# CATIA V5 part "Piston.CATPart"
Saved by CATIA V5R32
Part number: Piston
Bounding box of the stored display mesh (mm): x -46 to 46, y -45.932 to 45.932, z 0 to 70.683
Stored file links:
  D:\PROJECTS\Project 2022\CATIA V5 6R 2022\Resources\Part Files\c13_catia_v5_6r2022_prt\c13_catia_v5-6r2022_figr_13-41\Part & Asm files\Piston.CATPart
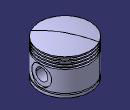
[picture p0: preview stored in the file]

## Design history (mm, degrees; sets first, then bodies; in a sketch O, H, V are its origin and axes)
Body1 (main body)
  Sketch1 on yz-plane, origin (0, 0, 0), H (0, 1, 0), V (0, 0, 1)
    line L1 (37, 0) -> (46, 0)
    line L2 (46, 0) -> (46, 5)
    construction line L3 (0, 62) -> (0, 0)
    point P2 (46, 65)
    line L4 (42.5, 45) -> (42.5, 48)
    point P5 (46, 48)
    point P6 (46, 50)
    point P7 (46, 53)
    point P8 (46, 55)
    point P9 (46, 58)
    point P10 (46, 60)
    line L5 (42.5, 48) -> (46, 48)
    line L6 (42.5, 45) -> (46, 45)
    line L7 (42.5, 50) -> (46, 50)
    point P13 (42.5, 50)
    line L8 (42.5, 53) -> (46, 53)
    point P14 (42.5, 53)
    line L9 (42.5, 55) -> (46, 55)
    point P15 (42.5, 55)
    line L10 (42.5, 58) -> (46, 58)
    point P16 (42.5, 58)
    line L11 (42.5, 60) -> (46, 60)
    point P17 (42.5, 60)
    line L12 (46, 48) -> (46, 50)
    line L13 (46, 53) -> (46, 55)
    line L14 (46, 58) -> (46, 60)
    line L15 (42.5, 50) -> (42.5, 53)
    line L16 (42.5, 55) -> (42.5, 58)
    line L17 (42.5, 60) -> (42.5, 63)
    line L18 (42.5, 63) -> (46, 63)
    point P18 (46, 63)
    line L19 (46, 63) -> (46, 65)
    line L20 (46, 5) -> (42.5, 5)
    point P20 (42.5, 5)
    line L21 (42.5, 5) -> (42.5, 7)
    line L22 (42.5, 7) -> (46, 7)
    point P22 (46, 7)
    line L23 (46, 7) -> (46, 45)
    point P23 (-46, 65)
    point P24 (-46, 63)
    construction line L24 (-46, 63) -> (-46, 65)
    arc A1 centre (0, -118.3167) radius 189 from (46, 65) to (0, 70.6833) ccw
    point P26 (0, 55)
    line L25 (37, 0) -> (37, 62)
    line L26 (37, 62) -> (0, 62)
    line L27 (0, 62) -> (0, 70.6833)
    construction arc A2 centre (0, -118.3167) radius 189 from (0, 70.6833) to (-46, 65) ccw
    distance L2 L4 = 3.5
    distance L6 L1 = 45
    length L4 = 3
    length L15 = 3
    length L16 = 3
    length L13 = 2
    length L12 = 2
    length L17 = 3
    length L19 = 2
    length L14 = 2
    length L21 = 2
    distance L1 L22 = 7
    radius A1 = 189
    length L26 = 37
    length L25 = 62
    distance L2 L3 = 46
    horizontal: L1 H, L5 H, L6 H, L7 H, L8 H, L9 H, L10 H, L11 H, L18 H, L20 H, L22 H, L26 H
    vertical: L2 V, L3 V, L12 V, L13 V, L14 V, L19 V, L21 V, L23 V, L25 V, L27 V, L17 V, L16 V, L15 V, L4 V
    coincidence: L2 P5, L2 P6, L2 P7, L2 P8, L2 P9, L2 P10, L4 P13, L4 P14, L4 P15, L4 P16, L4 P17, L2 L12, L12 L13, L13 L14, L4 L15, L15 L16, L16 L17, P18 L14, L14 L19, P20 L15, P22 L2, L2 L23, P26 L3, P26 L9, L1 H, A1 A2
    symmetry: P2 P23 L3, P18 P24 L3, L19 L24 L3
  Shaft1: profile Sketch1, axis Sketch1.V, angle 360
  Sketch2 on yz-plane, origin (0, 0, 0), H (0, 1, 0), V (0, 0, 1)
    circle A1 centre (0, 26) radius 19.5
    point P1 (0, 26)
    radius A1 = 19.5
    distance H P1 = 26
    coincidence: P1 V
  Pad1: profile Sketch2, direction (1, 0, 0), up to the existing solid (limit type 2), opposite side length -25
  Mirror1: of Pad1, Sketch2, about yz-plane
  Sketch3 on yz-plane, origin (0, 0, 0), H (0, 1, 0), V (0, 0, 1)
    circle A1 centre (0, 26) radius 18
    point P1 (0, 26)
    reference projected circle E1 centre (0, 26) radius 19.5 from edge of Pad1
    radius A1 = 18
    coincidence: P1 V
    concentricity: A1 E1
  Pocket1: profile Sketch3, direction (-1, 0, 0), length 42.5, opposite side length -50
  Mirror2: of Pocket1, Sketch3, about yz-plane
  Sketch4 on yz-plane, origin (0, 0, 0), H (0, 1, 0), V (0, 0, 1)
    circle A1 centre (0, 26) radius 11
    point P1 (0, 26)
    reference projected circle E1 centre (0, 26) radius 19.5 from edge of Pad1
    radius A1 = 11
    coincidence: P1 V
    concentricity: A1 E1
  Pocket2: profile Sketch4, direction (-1, 0, 0), length 50.5, mirrored extent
